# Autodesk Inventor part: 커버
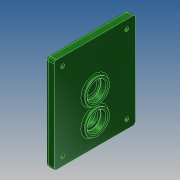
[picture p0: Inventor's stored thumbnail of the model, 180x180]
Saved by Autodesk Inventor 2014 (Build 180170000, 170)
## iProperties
Created: 2016-02
Part Number: 커버
Material: 알루미늄 6061
Document SubType Name: Modeling
Designer: mduedu
Density: 1 g/cm^3
Appearance: 매끄러움 - 짙은 산림 녹색
Mass: 100.463 g
Surface Area: 266.629 cm^2
Volume: 100.463 cm^3
Author: mduedu
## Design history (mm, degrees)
sketch "스케치1"
  geometry: L1 (63, 47)-(-47, 47); L2 (-47, 47)-(-47, -47); L3 (-47, -47)-(63, -47); L4 (63, -47)-(63, 47); 2 further points
  constraints: 8 end point, 2 parallel, 1 horizontal, 1 horizontal alignment, 1 midpoint, 1 perpendicular
  dimensions: "d102" = 94 distance of L3.end L1.start; "d104" = 47 distance from line of L2 point (0, 0); "d105" = 110 distance of L1.start L1.end
extrude "돌출1" new body sketch "스케치1" distance "d1" = 10; taper "d2" = 0 deg
sketch "스케치2"
  geometry: C1 r 14 at (0, 11); 1 further point
  constraints: 1 centre point, 1 vertical alignment
  dimensions: "d3" = 28 diameter of C1; "d6" = 11 distance of C1.centre point (0, 0)
extrude "돌출2" join sketch "스케치2" distance "d7" = 3; taper "d8" = 0 deg
sketch "스케치3"
  geometry: C1 r 14 at (0, -20); 1 further point
  constraints: 1 centre point, 1 vertical alignment
  dimensions: "d9" = 28 diameter of C1; "d10" = 20 distance of C1.centre point (0, 0)
extrude "돌출3" join sketch "스케치3" distance "d11" = 3; taper "d12" = 0 deg
hole "구멍1" diameter "d15" = 22; stored, may be unused: countersink angle "d19" = 90 deg, drill point angle "d21" = 0 deg; dims "d13" = 10, "d14" = 10, "d16" = 6, "d17" = 4, "d18" = 2, "d20" = 7
hole "구멍2" diameter "d24" = 18; stored, may be unused: countersink angle "d28" = 90 deg, drill point angle "d30" = 0 deg; dims "d22" = 10, "d23" = 10, "d25" = 6, "d26" = 4, "d27" = 2, "d29" = 1
hole "구멍3" diameter "d33" = 22; stored, may be unused: countersink angle "d37" = 90 deg, drill point angle "d39" = 0 deg; dims "d34" = 6, "d35" = 4, "d36" = 2, "d38" = 7, "d73" = 10, "d74" = 10
sketch "스케치4"
  geometry: C1 r 14 at (0, -20) reference; C2 r 18 at (0, -20); 1 further point
  constraints: 1 centre point, 1 coincident
  dimensions: "d40" = 36 diameter of C2
extrude "돌출4" join sketch "스케치4" distance "d41" = 4; taper "d42" = 0 deg
hole "구멍4" diameter "d45" = 22; stored, may be unused: countersink angle "d49" = 90 deg, drill point angle "d51" = 0 deg; dims "d43" = 10, "d44" = 10, "d46" = 6, "d47" = 4, "d48" = 2, "d50" = 7
hole "구멍5" diameter "d54" = 15; stored, may be unused: countersink angle "d58" = 90 deg, drill point angle "d60" = 0 deg; dims "d52" = 10, "d53" = 10, "d55" = 6, "d56" = 4, "d57" = 2, "d59" = 7
fillet "모깎기1" dims "d61" = 0.3
fillet "모깎기2" dims "d62" = 2
chamfer "모따기1" distance "d63" = 1; stored, may be unused: second distance "d64" = 2, angle "d65" = 45 deg
fillet "모깎기6" dims "d88" = 2
fillet "모깎기4" dims "d75" = 2
sketch "스케치9"
  geometry: L1 (47, 63)-(47, -47) reference; L2 (-47, 63)-(47, 63) reference; L3 (-47, -47)-(-47, 63) reference; L4 (47, -47)-(-47, -47) reference; L5 (37, 53)-(37, -37); L6 (37, -37)-(-37, -37); L7 (-37, -37)-(-37, 53); L8 (-37, 53)-(37, 53); C1 r 20 at (0, -20) reference; 5 further points
  constraints: 8 end point, 4 coincident, 3 other
  dimensions: "d107" = 10 distance between parallel lines of L8 L2
hole "구멍7" sketch "스케치9" at (-37, 53), (37, 53), (37, -37), (-37, -37) diameter "d108" = 4.5; stored, may be unused: countersink angle "d112" = 90 deg, drill point angle "d114" = 118 deg; dims "d109" = 6, "d110" = 8, "d111" = 4.6, "d113" = 8
fillet "모깎기8" dims "d106" = 3
fillet "모깎기9" dims "d115" = 3
node "솔리드1"
node "투영된 루프2"
